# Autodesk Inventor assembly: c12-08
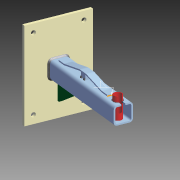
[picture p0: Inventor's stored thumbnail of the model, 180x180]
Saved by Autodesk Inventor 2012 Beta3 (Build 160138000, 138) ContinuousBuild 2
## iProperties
Created: 2011-01
Part Number: c12-08
Document SubType Name: Weldment
Designer: Beta-8540w
Weld Material: Welded Steel Mild
_SolveAssemblyDoc: Frame Generator Solve Assembly
_Version: 15.0.0
Author: Beta-8540w
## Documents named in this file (5)
- C:\Inventor 2012 Essentials\Assemblies\Chapter 12\c12-08.iam
- C:\Inventor 2012 Essentials\Parts\Chapter 12\c12-01.ipt
- C:\Inventor 2012 Essentials\Parts\Chapter 12\c12-02.ipt
- C:\Inventor 2012 Essentials\Assemblies\Chapter 12\Frame\Frame c12-01.iam
- C:\Inventor 2012 Essentials\Parts\Chapter 12\c12-03.ipt
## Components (4 placed, 4 different names)
1. c12-01:1 — Mate:2
2. c12-02:1 — Flush:1
3. Frame c12-01:1 [sub-assembly] — Mate:3
4. c12-03:1 — Mate:1, Mate:2, Mate:3
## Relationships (4: Mate 3, Flush 1)
- Flush:1: c12-02:1
- Mate:1: c12-03:1
- Mate:2: c12-01:1 ↔ c12-03:1
- Mate:3: Frame c12-01:1 ↔ c12-03:1
